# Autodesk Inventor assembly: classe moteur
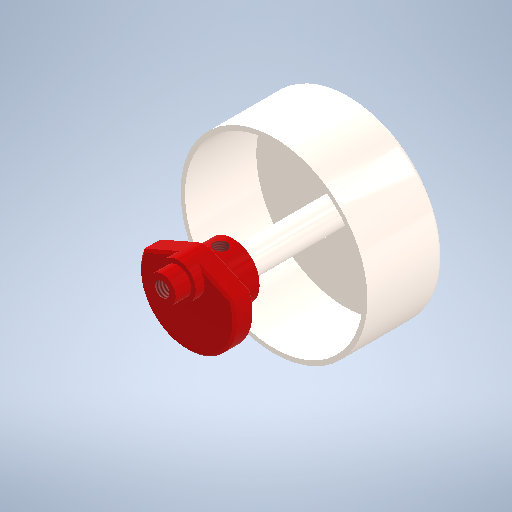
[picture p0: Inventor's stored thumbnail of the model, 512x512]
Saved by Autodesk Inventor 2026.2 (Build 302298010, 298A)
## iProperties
Created: 1601-01
Part Number: classe moteur
Document SubType Name: Assembly
Designer: mel
Part Number: Appareil_de_massage
Sending System: SOLIDWORKS 2023
Last Saved Date: 2025-04-02
Author: mel
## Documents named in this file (3)
- C:\Users\mel\Downloads\18256-itec-20250709t050547z-1-001 (1)\ITEC\Ressources\ITEC00_SW_Appareil_de_massage\S1Appareil_de_massage\S1Appareil_de_massage\classe moteur.iam
- C:\Users\mel\Downloads\18256-itec-20250709t050547z-1-001 (1)\ITEC\Ressources\ITEC00_SW_Appareil_de_massage\S1Appareil_de_massage\S1Appareil_de_massage\S1BrushlessAxe_moteur.ipt
- C:\Users\mel\Downloads\18256-itec-20250709t050547z-1-001 (1)\ITEC\Ressources\ITEC00_SW_Appareil_de_massage\S1Appareil_de_massage\S1Appareil_de_massage\S1Manivellebeaune.ipt
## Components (2 placed, 2 different names)
1. BrushlessAxe_moteur-2 — Logement:1
2. S1Manivellebeaune:1 — Logement:1
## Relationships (1: Insert 1)
- Logement:1 [Insert]: BrushlessAxe_moteur-2 ↔ S1Manivellebeaune:1
